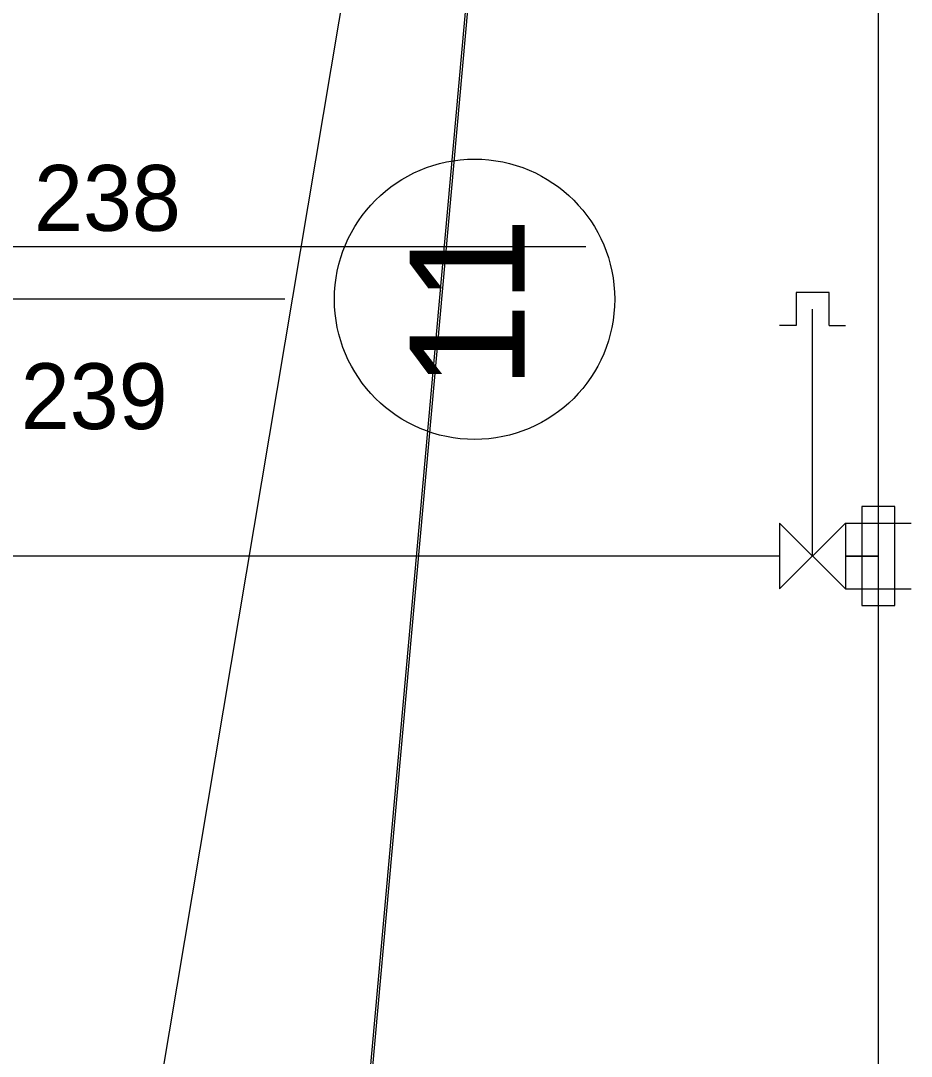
# Model space of a CAD drawing. Extents: x -264205 to -263659, y -1242401 to -1242060.
# Drawn here: x -263794.66 to -263787.89, y -1242152.63 to -1242144.77 of the extents above; entities that cross this region are included whole.
import ezdxf

# ---------------------------------------------------------------- set-up
doc = ezdxf.new("R2010")
doc.units = 0
for name, color, linetype in [('BOD_CISLO', 7, 'Continuous'), ('KFA_SO_10-1_PLACHTY', 7, 'Continuous'), ('OSI_STAVBY_KFA', 7, 'Continuous'), ('SITUACIA_DSP_2D', 7, 'Continuous')]:
    doc.layers.add(name, color=color, linetype=linetype)

msp = doc.modelspace()

# ---------------------------------------------------------------- linework, layer by layer
at = {"layer": 'KFA_SO_10-1_PLACHTY'}
msp.add_lwpolyline([(-263792.711, -1242160.574), (-263792.693, -1242160.586), (-263790.23, -1242133.231), (-263790.248, -1242133.216)], close=True, dxfattribs=at)
msp.add_lwpolyline([(-263790.3095, -1242133.2663), (-263794.6437, -1242159.079), (-263794.8712, -1242160.3355)], dxfattribs=at)
at = {"layer": 'OSI_STAVBY_KFA'}
for q in [(-263909.3428, -1242146.8822), (-263792.6528, -1242146.8822)]:
    msp.add_line((-263792.6528, -1242146.8822), q, dxfattribs=at)
msp.add_circle((-263791.2101, -1242146.8825), 1.0643, dxfattribs=at)
at = {"layer": 'SITUACIA_DSP_2D'}
for p, q in [((-263788.1428, -1242233.636), (-263788.1428, -1242082.6399)), ((-263795.2178, -1242146.4822), (-263790.3642, -1242146.4822)), ((-263788.7679, -1242146.8322), (-263788.7679, -1242147.0822)), ((-263788.5179, -1242146.8322), (-263788.7679, -1242146.8322)), ((-263788.5179, -1242147.0822), (-263788.5179, -1242146.8322)), ((-263788.6428, -1242148.8322), (-263788.6429, -1242146.9572)), ((-263788.7679, -1242147.0822), (-263788.8929, -1242147.0822)), ((-263788.5179, -1242147.0822), (-263788.3929, -1242147.0822)), ((-263788.2678, -1242148.4572), (-263788.2678, -1242149.2072)), ((-263788.0178, -1242148.4572), (-263788.2678, -1242148.4572)), ((-263788.0178, -1242149.2072), (-263788.0178, -1242148.4572)), ((-263788.8928, -1242148.5822), (-263788.8929, -1242149.0822)), ((-263788.8929, -1242149.0822), (-263788.3928, -1242148.5822)), ((-263788.3929, -1242149.0822), (-263788.8928, -1242148.5822)), ((-263788.3928, -1242148.5822), (-263788.3929, -1242149.0822)), ((-263788.3928, -1242148.5822), (-263787.8928, -1242148.5822)), ((-263788.8928, -1242148.8322), (-263800.5928, -1242148.8322)), ((-263788.1428, -1242148.8322), (-263788.3928, -1242148.8322)), ((-263788.3928, -1242148.8322), (-263788.1428, -1242148.8322)), ((-263788.3929, -1242149.0822), (-263787.8928, -1242149.0822)), ((-263788.2678, -1242149.2072), (-263788.0178, -1242149.2072))]:
    msp.add_line(p, q, dxfattribs=at)

# ---------------------------------------------------------------- texts
at = {"layer": 'BOD_CISLO'}
for s, p in [('238', (-263794.5568, -1242146.3631)), ('239', (-263794.6574, -1242147.8685))]:
    msp.add_text(s, height=0.5, dxfattribs=at).set_placement(p)
at = {"layer": 'OSI_STAVBY_KFA'}
msp.add_text('11', height=0.875, rotation=90, dxfattribs=at).set_placement((-263790.8295, -1242147.5623))

doc.saveas('drawing.dxf')
